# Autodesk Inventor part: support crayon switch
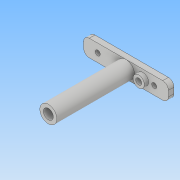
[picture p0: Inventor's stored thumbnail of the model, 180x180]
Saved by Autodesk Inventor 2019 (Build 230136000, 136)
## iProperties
Created: 2024-08
Part Number: support crayon switch
Material: Générique
Document SubType Name: Modeling
Designer: admin
Density: 1 g/cm^3
Appearance: Par défaut
Author: admin
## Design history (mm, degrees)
sketch "Esquisse1"
  geometry: L1 (-30, 6)-(30, 6); L2 (30, 6)-(30, -6); L3 (30, -6)-(-30, -6); L4 (-30, -6)-(-30, 6); C1 r 1.75 at (-20, 0); C2 r 1.75 at (20, 0); 1 further point
  constraints: 8 end point, 2 centre point, 2 parallel, 1 horizontal, 1 perpendicular
  dimensions: "d0" = 60 distance of L1.start L1.end; "d1" = 12 distance of L3.end L1.start; "d2" = 6 distance from line of L1 point (0, 0) (= 0.5 x d1); "d3" = 30 distance from line of point (0, 0) L4 (= 0.5 x d0); "d4" = 3.5 diameter of C1; "d5" = 3.5 diameter of C2; "d6" = 20 distance of point (0, 0) C1.centre; "d7" = 20 distance of C2.centre point (0, 0)
extrude "Extrusion1" new body sketch "Esquisse1" distance "d8" = 4; taper "d9" = 0 deg
fillet "Congé1" dims "d10" = 4
sketch "Esquisse2"
  geometry: C1 r 6 at (0, 0); C2 r 3.5 at (0, 0); 1 further point
  constraints: 2 centre point, 2 coincident
  dimensions: "d11" = 7 diameter of C2; "d12" = 12 diameter of C1
extrude "Extrusion2" join sketch "Esquisse2" distance "d13" = 55; taper "d14" = 0 deg
fillet "Congé2" dims "d15" = 2
sketch "Esquisse3"
  geometry: C1 r 2.1 at (12, 0); 1 further point
  constraints: 1 centre point
  dimensions: "d16" = 4.2 diameter of C1; "d22" = 12 distance of point (0, 0) C1.centre
extrude "Extrusion3" cut sketch "Esquisse3" extent not by distance; stored distance "d17" = 55; taper "d18" = 0 deg
sketch "Esquisse4"
  geometry: C1 r 2.1 at (12, 0) reference; C2 r 4 at (12, 0); 1 further point
  constraints: 1 centre point, 1 coincident
  dimensions: "d19" = 8 diameter of C2
extrude "Extrusion4" join sketch "Esquisse4" distance "d20" = 3; taper "d21" = 0 deg
node "Solide1"
